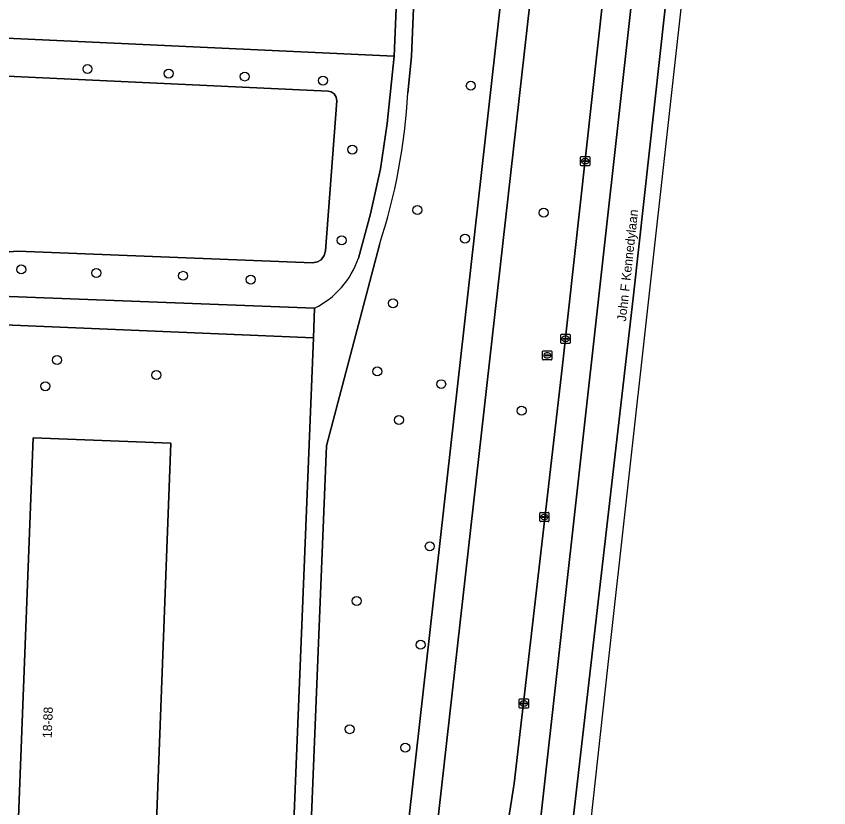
# Model space of a CAD drawing. Extents: x 161354 to 162026, y 386504 to 387460.
# Drawn here: x 161895 to 161983.7, y 386817.3 to 386903.7 of the extents above; entities that cross this region are included whole.
import ezdxf

# ---------------------------------------------------------------- set-up
doc = ezdxf.new("R2010")
doc.units = 0
for name, color, linetype in [('IMGEO_Berm_groen', 7, 'Continuous'), ('IMGEO_Boom', 7, 'Continuous'), ('IMGEO_Erf', 7, 'Continuous'), ('IMGEO_Fietspad_gesloten', 7, 'Continuous'), ('IMGEO_Groenvoorziening', 7, 'Continuous'), ('IMGEO_Kolk', 7, 'Continuous'), ('IMGEO_Loofbos', 7, 'Continuous'), ('IMGEO_Openbare_ruimte_label', 7, 'Continuous'), ('IMGEO_Pand', 7, 'Continuous'), ('IMGEO_Pand_nummerreeks', 7, 'Continuous'), ('IMGEO_Rijbaan_regionaal_gesloten', 7, 'Continuous'), ('IMGEO_Rioolput', 7, 'Continuous'), ('IMGEO_Voetpad_halfverhard', 7, 'Continuous'), ('IMGEO_Voetpad_open', 7, 'Continuous')]:
    doc.layers.add(name, color=color, linetype=linetype)

msp = doc.modelspace()

# ---------------------------------------------------------------- linework, layer by layer
at = {"layer": 'IMGEO_Berm_groen'}
for points in [[(161967.257, 387050.915), (161961.639, 387000), (161960.38, 386987.709), (161938.796, 386796.287), (161936.822, 386778.776), (161933.448, 386750), (161933.024, 386747.211), (161931.111, 386738.486), (161920.088, 386699.556), (161913.466, 386677.408), (161909.577, 386666.417)], [(161931.854, 386730.957), (161936.419, 386750), (161939.69, 386764.511), (161941.551, 386773.496), (161945.484, 386795.546), (161945.681, 386796.648), (161949.337, 386819.995), (161954.584, 386865.29), (161962.329, 386935.471), (161969.651, 387000), (161975.237, 387050.12)]]:
    msp.add_lwpolyline(points, dxfattribs=at)
at = {"layer": 'IMGEO_Boom'}
for centre in [(161902.772, 386897.941), (161911.628, 386897.435), (161919.941, 386897.113), (161928.469, 386896.674), (161944.607, 386896.107), (161931.684, 386889.146), (161938.784, 386882.552), (161952.562, 386882.256), (161930.506, 386879.242), (161943.966, 386879.421), (161895.541, 386876.067), (161903.739, 386875.683), (161913.207, 386875.373), (161920.592, 386874.96), (161936.117, 386872.378), (161899.447, 386866.187), (161934.394, 386864.938), (161910.279, 386864.551), (161898.166, 386863.328), (161941.376, 386863.554), (161950.146, 386860.658), (161936.759, 386859.642), (161940.133, 386845.864), (161932.155, 386839.897), (161939.122, 386835.12), (161931.387, 386825.912), (161937.453, 386823.897)]:
    msp.add_circle(centre, 0.489, dxfattribs=at)
at = {"layer": 'IMGEO_Erf'}
for points in [[(161885.264, 386901.684), (161936.238, 386899.338), (161940.02, 386989.533), (161894.944, 386991.428)], [(161924.564, 386797.865), (161927.422, 386868.613), (161882.453, 386870.503), (161880.002, 386810.68)]]:
    msp.add_lwpolyline(points, dxfattribs=at)
msp.add_lwpolyline([(161913.152, 386800.384), (161909.441, 386800.524), (161909.643, 386805.996), (161907.977, 386806.059), (161907.851, 386802.75), (161907.636, 386797.054), (161894.551, 386797.549), (161894.767, 386803.245), (161894.787, 386803.785), (161895.261, 386816.317), (161896.826, 386857.698), (161911.872, 386857.129), (161909.945, 386806.18), (161913.367, 386806.05), (161917.079, 386805.91), (161916.864, 386800.243)], close=True, dxfattribs=at)
at = {"layer": 'IMGEO_Fietspad_gesloten'}
for points in [[(161964.191, 387051.221), (161958.492, 387000), (161935.661, 386796.635)], [(161938.796, 386796.287), (161960.38, 386987.709), (161961.639, 387000), (161967.257, 387050.915)]]:
    msp.add_lwpolyline(points, dxfattribs=at)
at = {"layer": 'IMGEO_Groenvoorziening'}
for points in [[(161932.333, 386877.3), (161933.646, 386882.14), (161934.755, 386887.031), (161935.485, 386891.976), (161936.238, 386899.338), (161885.264, 386901.684)], [(161894.235, 386878.004), (161895.177, 386878.066), (161927.326, 386876.807), (161927.892, 386876.905), (161928.264, 386877.127), (161928.619, 386877.579), (161928.756, 386878.084), (161929.974, 386894.457), (161929.918, 386894.869), (161929.699, 386895.223), (161929.355, 386895.458), (161929.023, 386895.531), (161889.282, 386897.359)], [(161889.282, 386897.359), (161929.023, 386895.531), (161929.355, 386895.458), (161929.699, 386895.223), (161929.918, 386894.869), (161929.974, 386894.457), (161928.756, 386878.084), (161928.619, 386877.579), (161928.264, 386877.127), (161927.892, 386876.905), (161927.326, 386876.807), (161895.177, 386878.066), (161894.235, 386878.004)], [(161889.446, 386873.296), (161927.553, 386871.852)]]:
    msp.add_lwpolyline(points, dxfattribs=at)
msp.add_arc((161923.421, 386880.299), 9.403, 296.06939, 341.40407, dxfattribs=at)
at = {"layer": 'IMGEO_Kolk'}
for p, q in [((161956.588, 386887.453), (161956.588, 386888.305)), ((161956.663, 386888.379), (161957.515, 386888.379)), ((161956.847, 386887.873), (161956.847, 386887.885)), ((161957.285, 386887.836), (161956.887, 386887.836)), ((161956.89, 386887.922), (161957.288, 386887.922)), ((161957.099, 386887.599), (161957.074, 386887.599)), ((161957.076, 386888.159), (161957.101, 386888.159)), ((161957.331, 386887.885), (161957.331, 386887.873)), ((161957.589, 386888.305), (161957.589, 386887.453)), ((161957.515, 386887.379), (161956.663, 386887.379)), ((161954.441, 386868.076), (161954.441, 386868.928)), ((161954.516, 386869.002), (161955.368, 386869.002)), ((161955.442, 386868.928), (161955.442, 386868.076)), ((161955.368, 386868.002), (161954.516, 386868.002)), ((161954.7, 386868.496), (161954.7, 386868.508)), ((161955.138, 386868.459), (161954.74, 386868.459)), ((161954.743, 386868.545), (161955.141, 386868.545)), ((161954.952, 386868.222), (161954.927, 386868.222)), ((161954.929, 386868.782), (161954.954, 386868.782)), ((161955.184, 386868.508), (161955.184, 386868.496)), ((161952.14, 386848.637), (161952.14, 386849.489)), ((161952.215, 386849.563), (161953.067, 386849.563)), ((161953.141, 386849.489), (161953.141, 386848.637)), ((161953.067, 386848.563), (161952.215, 386848.563)), ((161952.399, 386849.057), (161952.399, 386849.069)), ((161952.837, 386849.02), (161952.439, 386849.02)), ((161952.442, 386849.106), (161952.84, 386849.106)), ((161952.651, 386848.783), (161952.626, 386848.783)), ((161952.628, 386849.343), (161952.653, 386849.343)), ((161952.883, 386849.069), (161952.883, 386849.057)), ((161949.896, 386828.288), (161949.896, 386829.14)), ((161949.971, 386829.214), (161950.823, 386829.214)), ((161950.384, 386828.994), (161950.409, 386828.994)), ((161950.897, 386829.14), (161950.897, 386828.288)), ((161950.823, 386828.214), (161949.971, 386828.214)), ((161950.155, 386828.708), (161950.155, 386828.72)), ((161950.593, 386828.671), (161950.195, 386828.671)), ((161950.198, 386828.757), (161950.596, 386828.757)), ((161950.407, 386828.434), (161950.382, 386828.434)), ((161950.639, 386828.72), (161950.639, 386828.708))]:
    msp.add_line(p, q, dxfattribs=at)
for points in [[(161956.588, 386887.453), (161956.588, 386888.305)], [(161956.663, 386888.379), (161957.515, 386888.379)], [(161957.589, 386888.305), (161957.589, 386887.453)], [(161957.515, 386887.379), (161956.663, 386887.379)], [(161954.441, 386868.076), (161954.441, 386868.928)], [(161954.516, 386869.002), (161955.368, 386869.002)], [(161955.442, 386868.928), (161955.442, 386868.076)], [(161955.368, 386868.002), (161954.516, 386868.002)], [(161952.14, 386848.637), (161952.14, 386849.489)], [(161952.215, 386849.563), (161953.067, 386849.563)], [(161953.141, 386849.489), (161953.141, 386848.637)], [(161953.067, 386848.563), (161952.215, 386848.563)], [(161949.896, 386828.288), (161949.896, 386829.14)], [(161949.971, 386829.214), (161950.823, 386829.214)], [(161950.897, 386829.14), (161950.897, 386828.288)], [(161950.823, 386828.214), (161949.971, 386828.214)]]:
    msp.add_lwpolyline(points, dxfattribs=at)
for centre, radius, start, end in [((161956.665, 386888.303), 0.0765, 91.55205, 178.44795), ((161956.665, 386888.303), 0.0765, 91.55205, 178.44795), ((161956.887, 386887.882), 0.0403, 85.87752, 175.75265), ((161956.884, 386887.872), 0.0366, 178.93798, 274.71019), ((161957.288, 386887.879), 0.043, 264.86636, 352.45326), ((161957.292, 386887.884), 0.0386, 1.73085, 96.63898), ((161957.513, 386888.303), 0.0765, 1.55205, 88.44795), ((161957.513, 386888.303), 0.0765, 1.55205, 88.44795), ((161956.665, 386887.455), 0.0765, 181.55205, 268.44795), ((161956.665, 386887.455), 0.0765, 181.55205, 268.44795), ((161957.513, 386887.455), 0.0765, 271.55205, 358.44795), ((161957.513, 386887.455), 0.0765, 271.55205, 358.44795), ((161954.518, 386868.926), 0.0765, 91.55205, 178.44795), ((161954.518, 386868.926), 0.0765, 91.55205, 178.44795), ((161955.366, 386868.926), 0.0765, 1.55205, 88.44795), ((161955.366, 386868.926), 0.0765, 1.55205, 88.44795), ((161954.518, 386868.078), 0.0765, 181.55205, 268.44795), ((161954.518, 386868.078), 0.0765, 181.55205, 268.44795), ((161954.74, 386868.505), 0.0403, 85.87752, 175.75265), ((161954.737, 386868.495), 0.0366, 178.93798, 274.71019), ((161955.141, 386868.502), 0.043, 264.86636, 352.45326), ((161955.145, 386868.507), 0.0386, 1.73085, 96.63898), ((161955.366, 386868.078), 0.0765, 271.55205, 358.44795), ((161955.366, 386868.078), 0.0765, 271.55205, 358.44795), ((161952.217, 386849.487), 0.0765, 91.55205, 178.44795), ((161952.217, 386849.487), 0.0765, 91.55205, 178.44795), ((161953.065, 386849.487), 0.0765, 1.55205, 88.44795), ((161953.065, 386849.487), 0.0765, 1.55205, 88.44795), ((161952.217, 386848.639), 0.0765, 181.55205, 268.44795), ((161952.217, 386848.639), 0.0765, 181.55205, 268.44795), ((161952.439, 386849.066), 0.0403, 85.87752, 175.75265), ((161952.436, 386849.056), 0.0366, 178.93798, 274.71019), ((161952.84, 386849.063), 0.043, 264.86636, 352.45326), ((161952.844, 386849.068), 0.0386, 1.73085, 96.63898), ((161953.065, 386848.639), 0.0765, 271.55205, 358.44795), ((161953.065, 386848.639), 0.0765, 271.55205, 358.44795), ((161949.973, 386829.138), 0.0765, 91.55205, 178.44795), ((161949.973, 386829.138), 0.0765, 91.55205, 178.44795), ((161950.821, 386829.138), 0.0765, 1.55205, 88.44795), ((161950.821, 386829.138), 0.0765, 1.55205, 88.44795), ((161949.973, 386828.29), 0.0765, 181.55205, 268.44795), ((161949.973, 386828.29), 0.0765, 181.55205, 268.44795), ((161950.195, 386828.717), 0.0403, 85.87752, 175.75265), ((161950.192, 386828.707), 0.0366, 178.93798, 274.71019), ((161950.596, 386828.714), 0.043, 264.86636, 352.45326), ((161950.6, 386828.719), 0.0386, 1.73085, 96.63898), ((161950.821, 386828.29), 0.0765, 271.55205, 358.44795), ((161950.821, 386828.29), 0.0765, 271.55205, 358.44795)]:
    msp.add_arc(centre, radius, start, end, dxfattribs=at)
for centre, major_axis, ratio, start_param, end_param in [((161957.075, 386887.879), (-0.387, 0.002), 0.722429, 4.712389, 7.853982), ((161957.1, 386887.879), (-0.39, 0.002), 0.717154, 1.570796, 4.712389), ((161954.928, 386868.502), (-0.387, 0.002), 0.722429, 4.712389, 7.853982), ((161954.953, 386868.502), (-0.39, 0.002), 0.717154, 1.570796, 4.712389), ((161952.627, 386849.063), (-0.387, 0.002), 0.722429, 4.712389, 7.853982), ((161952.652, 386849.063), (-0.39, 0.002), 0.717154, 1.570796, 4.712389), ((161950.383, 386828.714), (-0.387, 0.002), 0.722429, 4.712389, 7.853982), ((161950.408, 386828.714), (-0.39, 0.002), 0.717154, 1.570796, 4.712389)]:
    msp.add_ellipse(centre, major_axis=major_axis, ratio=ratio, start_param=start_param, end_param=end_param, dxfattribs=at)
at = {"layer": 'IMGEO_Loofbos'}
for points in [[(161913.776, 386748.036), (161911.767, 386689.472), (161913.777, 386689.388), (161921.99, 386717.644), (161927.704, 386738.292), (161930.041, 386748.73), (161930.197, 386750), (161932.945, 386772.439), (161935.661, 386796.635), (161958.492, 387000)], [(161941.407, 386975.097), (161941.082, 386970.072), (161938.146, 386899.309), (161937.723, 386895.33)], [(161934.625, 386878.764), (161928.843, 386856.82), (161926.455, 386797.655), (161925.213, 386766.868)]]:
    msp.add_lwpolyline(points, dxfattribs=at)
msp.add_arc((161874.409, 386898.598), 63.398, 341.76936, 357.04563, dxfattribs=at)
at = {"layer": 'IMGEO_Pand'}
msp.add_lwpolyline([(161907.851, 386802.75), (161907.977, 386806.059), (161909.643, 386805.996), (161909.651, 386806.191), (161909.945, 386806.18), (161911.872, 386857.129), (161896.826, 386857.698), (161895.261, 386816.317), (161894.787, 386803.785), (161894.767, 386803.245), (161894.551, 386797.549), (161907.636, 386797.054)], close=True, dxfattribs=at)
at = {"layer": 'IMGEO_Rijbaan_regionaal_gesloten'}
for points in [[(161953.318, 386794.679), (161962.379, 386873.244), (161976.049, 386997.238), (161981.984, 387049.448), (161978.469, 387049.798), (161974.354, 387011.236), (161973.137, 387000.209), (161967.661, 386954.866), (161949.872, 386795.06), (161946.557, 386765.215), (161942.589, 386729.489), (161942.439, 386728.019), (161926.424, 386570.316), (161923.246, 386535.823), (161922.934, 386532.145), (161926.119, 386532.024), (161929.934, 386573.912), (161932.687, 386601.55), (161933.498, 386609.431), (161933.982, 386612.625), (161940.783, 386677.087)], [(161978.469, 387049.798), (161975.237, 387050.12), (161969.651, 387000), (161962.329, 386935.471), (161954.584, 386865.29), (161949.337, 386819.995), (161945.681, 386796.648), (161945.484, 386795.546), (161946.236, 386795.463), (161949.151, 386795.14), (161949.872, 386795.06), (161967.661, 386954.866), (161973.137, 387000.209), (161974.354, 387011.236)], [(161928.749, 386531.924), (161935.094, 386600.16), (161938.388, 386635.586), (161940.62, 386659.585), (161959.612, 386832.977), (161983.673, 387049.28), (161981.984, 387049.448), (161976.049, 386997.238), (161962.379, 386873.244), (161953.318, 386794.679), (161940.783, 386677.087), (161933.982, 386612.625), (161933.498, 386609.431), (161932.687, 386601.55), (161929.934, 386573.912), (161926.119, 386532.024)]]:
    msp.add_lwpolyline(points, close=True, dxfattribs=at)
at = {"layer": 'IMGEO_Rioolput'}
for p, q in [((161952.448, 386866.266), (161952.448, 386867.118)), ((161952.523, 386867.192), (161953.375, 386867.192)), ((161953.449, 386867.118), (161953.449, 386866.266)), ((161952.707, 386866.686), (161952.707, 386866.698)), ((161953.145, 386866.649), (161952.747, 386866.649)), ((161952.75, 386866.735), (161953.148, 386866.735)), ((161952.959, 386866.412), (161952.934, 386866.412)), ((161952.936, 386866.972), (161952.961, 386866.972)), ((161953.191, 386866.698), (161953.191, 386866.686)), ((161953.375, 386866.192), (161952.523, 386866.192))]:
    msp.add_line(p, q, dxfattribs=at)
for points in [[(161952.448, 386866.266), (161952.448, 386867.118)], [(161952.523, 386867.192), (161953.375, 386867.192)], [(161953.449, 386867.118), (161953.449, 386866.266)], [(161953.375, 386866.192), (161952.523, 386866.192)]]:
    msp.add_lwpolyline(points, dxfattribs=at)
for centre, radius, start, end in [((161952.525, 386867.116), 0.0765, 91.55205, 178.44795), ((161952.525, 386867.116), 0.0765, 91.55205, 178.44795), ((161953.373, 386867.116), 0.0765, 1.55205, 88.44795), ((161953.373, 386867.116), 0.0765, 1.55205, 88.44795), ((161952.525, 386866.268), 0.0765, 181.55205, 268.44795), ((161952.525, 386866.268), 0.0765, 181.55205, 268.44795), ((161952.747, 386866.695), 0.0403, 85.87752, 175.75265), ((161952.744, 386866.685), 0.0366, 178.93798, 274.71019), ((161953.148, 386866.692), 0.043, 264.86636, 352.45326), ((161953.152, 386866.697), 0.0386, 1.73085, 96.63898), ((161953.373, 386866.268), 0.0765, 271.55205, 358.44795), ((161953.373, 386866.268), 0.0765, 271.55205, 358.44795)]:
    msp.add_arc(centre, radius, start, end, dxfattribs=at)
for centre, major_axis, ratio, start_param, end_param in [((161952.935, 386866.692), (-0.387, 0.002), 0.722429, 4.712389, 7.853982), ((161952.96, 386866.692), (-0.39, 0.002), 0.717154, 1.570796, 4.712389)]:
    msp.add_ellipse(centre, major_axis=major_axis, ratio=ratio, start_param=start_param, end_param=end_param, dxfattribs=at)
at = {"layer": 'IMGEO_Voetpad_halfverhard'}
for points in [[(161940.02, 386989.533), (161936.238, 386899.338), (161935.485, 386891.976), (161934.755, 386887.031), (161933.646, 386882.14), (161932.333, 386877.3)], [(161937.723, 386895.33), (161938.146, 386899.309), (161941.082, 386970.072)], [(161925.213, 386766.868), (161926.455, 386797.655), (161928.843, 386856.82), (161934.625, 386878.764)], [(161927.553, 386871.852), (161927.422, 386868.613), (161924.564, 386797.865), (161923.762, 386778.004), (161923.315, 386766.943)]]:
    msp.add_lwpolyline(points, dxfattribs=at)
for centre, radius, start, end in [((161874.409, 386898.598), 63.398, 341.76936, 357.04563), ((161923.421, 386880.299), 9.403, 296.06939, 341.40407)]:
    msp.add_arc(centre, radius, start, end, dxfattribs=at)
at = {"layer": 'IMGEO_Voetpad_open'}
msp.add_lwpolyline([(161882.453, 386870.503), (161927.422, 386868.613), (161927.553, 386871.852), (161889.446, 386873.296)], dxfattribs=at)

# ---------------------------------------------------------------- texts
at = {"layer": 'IMGEO_Openbare_ruimte_label'}
msp.add_text('John F Kennedylaan', height=1, rotation=83.74207, dxfattribs=at).set_placement((161961.539, 386870.367))
at = {"layer": 'IMGEO_Pand_nummerreeks'}
msp.add_text('18-88', height=1, rotation=87.83395, dxfattribs=at).set_placement((161898.868, 386824.919))

doc.saveas('drawing.dxf')
